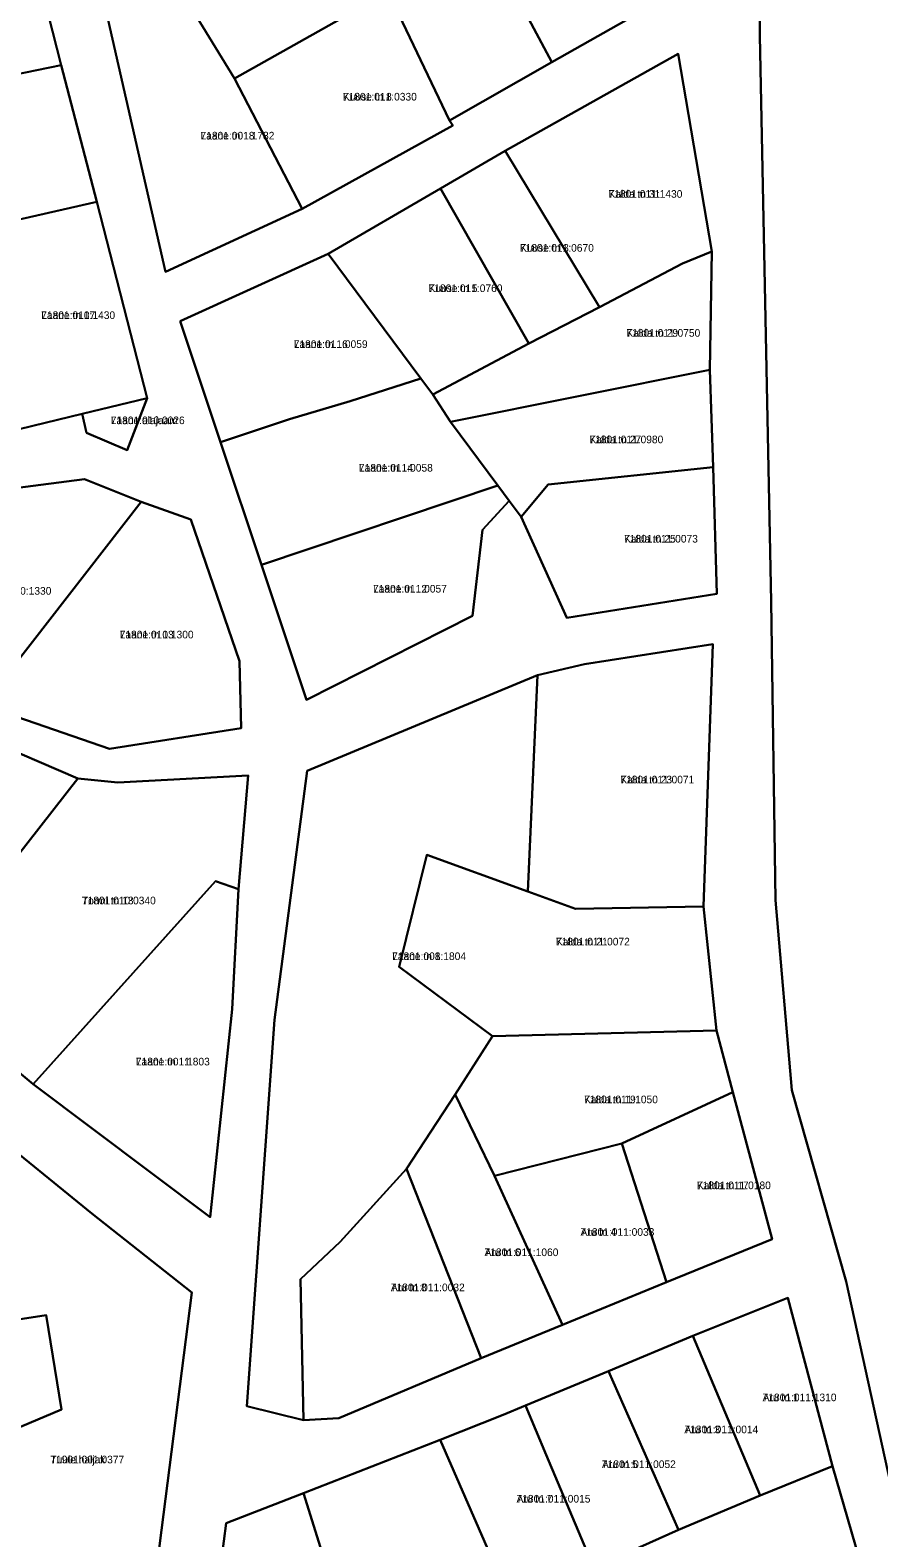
# Model space of a CAD drawing. Extents: x 529768 to 552006, y 6562269 to 6580975.
# Drawn here: x 537734.1 to 537900.7, y 6574495.4 to 6574791.4 of the extents above; entities that cross this region are included whole.
import ezdxf

# ---------------------------------------------------------------- set-up
doc = ezdxf.new("R2010")
doc.units = 0
for name, color, linetype in [('L_AADRESS', 7, 'Continuous'), ('PIIR', 7, 'Continuous'), ('TUNNUS', 7, 'Continuous')]:
    doc.layers.add(name, color=color, linetype=linetype)

msp = doc.modelspace()

# ---------------------------------------------------------------- linework, layer by layer
at = {"layer": 'PIIR'}
for points in [[(537747.59, 6574801.5), (537760.71, 6574743.92), (537787.55, 6574756.29), (537817.1, 6574772.66), (537816.46, 6574773.66), (537836.52, 6574785.11), (537855.61, 6574795.89), (537868.32, 6574802.94), (537866.69, 6574831.89), (537866.35, 6574865.77), (537843.83, 6574853.22), (537826.82, 6574844.29), (537809.98, 6574835.16), (537792.24, 6574825.71), (537758.6, 6574807.48)], [(537730.17, 6574824.12), (537740.19, 6574784.56), (537680.26, 6574772.23), (537691.03, 6574813.55)], [(537792.24, 6574825.71), (537807.06, 6574800.11), (537804.38, 6574798.9), (537774.23, 6574781.91), (537758.6, 6574807.48)], [(537836.52, 6574785.11), (537823.9, 6574808.82), (537841.02, 6574818.08), (537843.23, 6574819.29), (537855.61, 6574795.89)], [(537804.38, 6574798.9), (537807.06, 6574800.11), (537823.9, 6574808.82), (537836.52, 6574785.11), (537816.46, 6574773.66)], [(537760.71, 6574743.92), (537747.59, 6574801.5), (537758.6, 6574807.48), (537774.23, 6574781.91), (537787.55, 6574756.29)], [(537804.38, 6574798.9), (537816.46, 6574773.66), (537817.1, 6574772.66), (537787.55, 6574756.29), (537774.23, 6574781.91)], [(537763.6, 6574734.25), (537771.51, 6574710.5), (537779.52, 6574686.43), (537788.35, 6574659.92), (537820.98, 6574676.41), (537822.95, 6574693.31), (537828.16, 6574698.98), (537830.48, 6574695.87), (537839.48, 6574675.98), (537868.9, 6574680.7), (537868.22, 6574705.59), (537867.57, 6574724.71), (537867.97, 6574747.93), (537861.36, 6574786.76), (537827.35, 6574767.73), (537814.65, 6574760.32), (537792.65, 6574747.5)], [(537827.35, 6574767.73), (537861.36, 6574786.76), (537867.97, 6574747.93), (537862.21, 6574745.56), (537845.91, 6574736.98)], [(537701.22, 6574747.22), (537680.26, 6574772.23), (537740.19, 6574784.56), (537747.21, 6574757.72), (537715.55, 6574750.52)], [(537832.04, 6574729.87), (537814.65, 6574760.32), (537827.35, 6574767.73), (537845.91, 6574736.98)], [(537814.65, 6574760.32), (537832.04, 6574729.87), (537813.19, 6574719.84), (537810.84, 6574723.01), (537792.65, 6574747.5)], [(537715.55, 6574750.52), (537747.21, 6574757.72), (537757.08, 6574719.17), (537744.31, 6574716.08), (537724.64, 6574711.32)], [(537763.6, 6574734.25), (537792.65, 6574747.5), (537810.84, 6574723.01), (537796.92, 6574718.57), (537785.07, 6574715.03), (537771.51, 6574710.5)], [(537867.57, 6574724.71), (537816.64, 6574714.5), (537813.19, 6574719.84), (537832.04, 6574729.87), (537845.91, 6574736.98), (537862.21, 6574745.56), (537867.97, 6574747.93)], [(537771.51, 6574710.5), (537785.07, 6574715.03), (537796.92, 6574718.57), (537810.84, 6574723.01), (537813.19, 6574719.84), (537816.64, 6574714.5), (537825.91, 6574702.02), (537779.52, 6574686.43)], [(537816.64, 6574714.5), (537867.57, 6574724.71), (537868.22, 6574705.59), (537835.8, 6574702.2), (537830.48, 6574695.87), (537828.16, 6574698.98), (537825.91, 6574702.02)], [(537757.08, 6574719.17), (537753.17, 6574708.9), (537745.22, 6574712.32), (537744.31, 6574716.08)], [(537868.22, 6574705.59), (537868.9, 6574680.7), (537839.48, 6574675.98), (537830.48, 6574695.87), (537835.8, 6574702.2)], [(537695.84, 6574696.89), (537744.8, 6574703.27), (537755.94, 6574698.79), (537730.76, 6574666.33), (537727.86, 6574657.83), (537716.72, 6574665.41), (537722.15, 6574671.92), (537691.66, 6574690.88)], [(537779.52, 6574686.43), (537825.91, 6574702.02), (537828.16, 6574698.98), (537822.95, 6574693.31), (537820.98, 6574676.41), (537788.35, 6574659.92)], [(537730.76, 6574666.33), (537755.94, 6574698.79), (537765.64, 6574695.34), (537775.25, 6574667.49), (537775.57, 6574654.34), (537749.72, 6574650.29), (537727.86, 6574657.83)], [(537788.49, 6574645.95), (537782.11, 6574597.08), (537776.67, 6574521.21), (537787.8, 6574518.43), (537794.74, 6574518.83), (537822.69, 6574530.61), (537838.64, 6574537.15), (537859.02, 6574545.57), (537879.78, 6574554.03), (537872.04, 6574582.89), (537868.83, 6574594.96), (537866.31, 6574619.34), (537868.16, 6574670.82), (537842.95, 6574666.89), (537833.7, 6574664.78)], [(537833.7, 6574664.78), (537842.95, 6574666.89), (537868.16, 6574670.82), (537866.31, 6574619.34), (537841.15, 6574618.85), (537831.82, 6574622.25)], [(537787.18, 6574546.13), (537787.8, 6574518.43), (537776.67, 6574521.21), (537782.11, 6574597.08), (537788.49, 6574645.95), (537833.7, 6574664.78), (537831.82, 6574622.25), (537811.99, 6574629.47), (537806.55, 6574607.51), (537824.88, 6574593.89), (537817.59, 6574582.38), (537808.01, 6574567.83), (537795.01, 6574553.48)], [(537687.6, 6574621.29), (537708.94, 6574652.73), (537713.58, 6574660.3), (537724.92, 6574652.47), (537743.48, 6574644.48), (537711.65, 6574603.67)], [(537751.34, 6574643.68), (537776.94, 6574645.07), (537775.04, 6574622.73), (537770.48, 6574624.32), (537734.75, 6574584.44), (537711.65, 6574603.67), (537743.48, 6574644.48)], [(537811.99, 6574629.47), (537831.82, 6574622.25), (537841.15, 6574618.85), (537866.31, 6574619.34), (537868.83, 6574594.96), (537824.88, 6574593.89), (537806.55, 6574607.51)], [(537770.48, 6574624.32), (537775.04, 6574622.73), (537773.78, 6574599.17), (537769.48, 6574558.35), (537734.75, 6574584.44)], [(537824.88, 6574593.89), (537868.83, 6574594.96), (537872.04, 6574582.89), (537850.27, 6574572.79), (537825.29, 6574566.41), (537817.59, 6574582.38)], [(537825.29, 6574566.41), (537838.64, 6574537.15), (537822.69, 6574530.61), (537808.01, 6574567.83), (537817.59, 6574582.38)], [(537872.04, 6574582.89), (537879.78, 6574554.03), (537859.02, 6574545.57), (537850.26, 6574572.78)], [(537590.81, 6574472.39), (537630.48, 6574478.33), (537667.63, 6574492.48), (537677.14, 6574495.88), (537719.92, 6574511.97), (537740.27, 6574520.56), (537737.26, 6574539.11), (537730.94, 6574538.1), (537728.4, 6574555.96), (537725.42, 6574575.93), (537746.26, 6574559.07), (537765.85, 6574543.51), (537753.15, 6574444.02), (537739.55, 6574448.19)], [(537859.02, 6574545.57), (537838.64, 6574537.15), (537825.29, 6574566.41), (537850.26, 6574572.78)], [(537822.69, 6574530.61), (537794.74, 6574518.83), (537787.8, 6574518.43), (537787.18, 6574546.13), (537795.01, 6574553.48), (537808.01, 6574567.83)], [(537882.83, 6574542.46), (537891.61, 6574509.42), (537877.45, 6574503.68), (537864.2, 6574535.05)], [(537677.14, 6574495.88), (537671.97, 6574529.31), (537716.42, 6574535.9), (537730.94, 6574538.1), (537737.26, 6574539.11), (537740.27, 6574520.56), (537719.92, 6574511.97)], [(537847.65, 6574528.11), (537864.2, 6574535.05), (537877.45, 6574503.68), (537861.39, 6574496.93)], [(537847.65, 6574528.11), (537861.39, 6574496.93), (537850.01, 6574491.8), (537844.6, 6574489.93), (537835.4, 6574511.65), (537831.35, 6574521.34)], [(537814.61, 6574514.57), (537827, 6574519.49), (537831.35, 6574521.34), (537835.4, 6574511.65), (537844.6, 6574489.93), (537828.2, 6574483.4)], [(537787.81, 6574504.12), (537814.61, 6574514.57), (537828.2, 6574483.4), (537798.31, 6574470.39)], [(537898.38, 6574486.15), (537860.45, 6574466.26), (537850.01, 6574491.8), (537861.39, 6574496.93), (537877.45, 6574503.68), (537891.61, 6574509.42)], [(537787.81, 6574504.12), (537798.31, 6574470.39), (537804.36, 6574444.75), (537765.74, 6574445.21), (537772.61, 6574498.25)]]:
    msp.add_lwpolyline(points, close=True, dxfattribs=at)
for points in [[(537724.64, 6574711.32), (537744.31, 6574716.08), (537745.22, 6574712.32), (537753.17, 6574708.9), (537757.08, 6574719.17), (537747.21, 6574757.72), (537740.19, 6574784.56), (537730.17, 6574824.12)], [(537877.44, 6574804.07), (537877.38, 6574790.27), (537879.6, 6574679.21), (537880.42, 6574620.55), (537883.61, 6574583.23), (537894.34, 6574545.71), (537908.44, 6574481.23)], [(537954.55, 6574169.98), (537951.1, 6574224.38), (537959.6, 6574242.27), (537930.27, 6574387.38), (537908.44, 6574481.23), (537894.34, 6574545.71), (537883.61, 6574583.23), (537880.42, 6574620.55), (537879.6, 6574679.21), (537877.38, 6574790.27), (537877.44, 6574804.07)], [(537727.86, 6574657.83), (537749.72, 6574650.29), (537775.57, 6574654.34), (537775.25, 6574667.49), (537765.64, 6574695.34), (537755.94, 6574698.79), (537744.8, 6574703.27), (537695.84, 6574696.89)], [(537711.65, 6574603.67), (537734.75, 6574584.44), (537769.48, 6574558.35), (537773.78, 6574599.17), (537775.04, 6574622.73), (537776.94, 6574645.07), (537751.34, 6574643.68), (537743.48, 6574644.48), (537724.92, 6574652.47)], [(537590.81, 6574472.39), (537739.55, 6574448.19), (537753.15, 6574444.02), (537765.85, 6574543.51), (537746.26, 6574559.07), (537725.42, 6574575.93)], [(537898.38, 6574486.15), (537891.61, 6574509.42), (537882.83, 6574542.46), (537864.2, 6574535.05), (537847.65, 6574528.11), (537831.35, 6574521.34), (537827, 6574519.49), (537814.61, 6574514.57), (537787.81, 6574504.12), (537772.61, 6574498.25), (537765.74, 6574445.21)]]:
    msp.add_lwpolyline(points, dxfattribs=at)

# ---------------------------------------------------------------- texts
at = {"layer": 'L_AADRESS'}
for s, p in [('Kuuse tn 8', (537795.53, 6574777.59)), ('Laane tn 18', (537767.57, 6574769.94)), ('Kalda tn 31', (537847.66, 6574758.5)), ('Kuuse tn 3', (537830.28, 6574747.91)), ('Kuuse tn 5', (537812.34, 6574739.98)), ('Laane tn 17', (537736.31, 6574734.69)), ('Kalda tn 29', (537851.17, 6574731.21)), ('Laane tn 16', (537785.87, 6574729)), ('Lääne alajaam', (537749.96, 6574714.04)), ('Kalda tn 27', (537843.91, 6574710.29)), ('Laane tn 14', (537798.67, 6574704.72)), ('Kalda tn 25', (537850.7, 6574690.79)), ('Laane tn 12', (537801.43, 6574680.97)), ('Laane tn 13', (537751.71, 6574671.97)), ('Kalda tn 23', (537849.99, 6574643.5)), ('Tormi tn 13', (537744.29, 6574619.75)), ('Kalda tn 21', (537837.34, 6574611.68)), ('Laane tn 8', (537805.19, 6574608.81)), ('Laane tn 11', (537754.89, 6574588.12)), ('Kalda tn 19', (537842.85, 6574580.69)), ('Kalda tn 17', (537865.02, 6574563.82)), ('Aru tn 4', (537842.16, 6574554.66)), ('Aru tn 6', (537823.32, 6574550.68)), ('Aru tn 8', (537804.93, 6574543.78)), ('Aru tn 1', (537877.91, 6574522.18)), ('Aru tn 3', (537862.55, 6574515.89)), ('Tuule haljak', (537738.09, 6574509.98)), ('Aru tn 5', (537846.37, 6574509.06)), ('Aru tn 7', (537829.61, 6574502.28))]:
    msp.add_text(s, height=1.5, dxfattribs=at).set_placement(p)
at = {"layer": 'TUNNUS'}
for s, p in [('71801:011:0330', (537795.53, 6574777.59)), ('71801:001:1782', (537767.57, 6574769.94)), ('71801:011:1430', (537847.66, 6574758.5)), ('71801:011:0670', (537830.28, 6574747.91)), ('71801:011:0760', (537812.34, 6574739.98)), ('71801:010:1430', (537736.31, 6574734.69)), ('71801:011:0750', (537851.17, 6574731.21)), ('71801:011:0059', (537785.87, 6574729)), ('71801:010:0026', (537749.96, 6574714.04)), ('71801:011:0980', (537843.91, 6574710.29)), ('71801:011:0058', (537798.67, 6574704.72)), ('71801:011:0073', (537850.7, 6574690.79)), ('71801:010:1330', (537723.8, 6574680.56)), ('71801:011:0057', (537801.43, 6574680.97)), ('71801:010:1300', (537751.71, 6574671.97)), ('71801:011:0071', (537849.99, 6574643.5)), ('71801:010:0340', (537744.29, 6574619.75)), ('71801:001:1804', (537805.19, 6574608.81)), ('71801:011:0072', (537837.34, 6574611.68)), ('71801:001:1803', (537754.89, 6574588.12)), ('71801:011:1050', (537842.85, 6574580.69)), ('71801:011:0180', (537865.02, 6574563.82)), ('71801:011:0033', (537842.16, 6574554.66)), ('71801:011:1060', (537823.32, 6574550.68)), ('71801:011:0032', (537804.93, 6574543.78)), ('71801:011:1310', (537877.91, 6574522.18)), ('71801:011:0014', (537862.55, 6574515.89)), ('71901:001:0377', (537738.09, 6574509.98)), ('71801:011:0052', (537846.37, 6574509.06)), ('71801:011:0015', (537829.61, 6574502.28))]:
    msp.add_text(s, height=1.5, dxfattribs=at).set_placement(p)

doc.saveas('drawing.dxf')
